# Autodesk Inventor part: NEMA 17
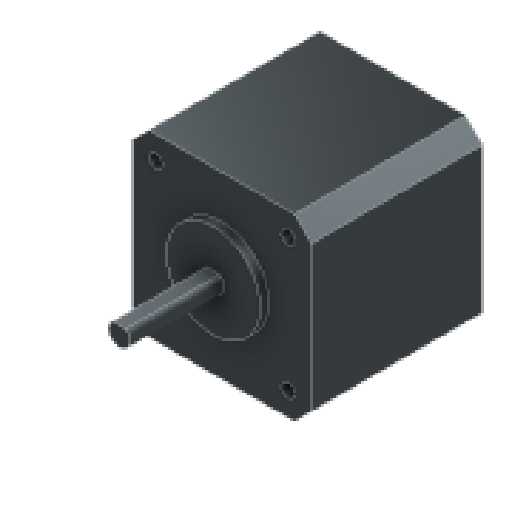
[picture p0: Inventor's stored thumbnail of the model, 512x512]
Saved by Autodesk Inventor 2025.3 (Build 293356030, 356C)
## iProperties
Created: 2026-03
Part Number: NEMA 17
Material: Generico
Description: NEMA 17
Document SubType Name: Modeling
Designer: R5800u
Density: 1 g/cm^3
Appearance: Grigio ferro
Author: R5800u
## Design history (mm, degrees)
node "NEMA 17"
sketch "Schizzo1"
  geometry: L1 (-2.707, 42)-(39.293, 42); L2 (39.293, 42)-(39.293, 0); L3 (39.293, 0)-(-2.707, 0); L4 (-2.707, 0)-(-2.707, 42); L5 (-2.707, 42)-(39.293, 0); L6 (39.293, 42)-(-2.707, 0); L7 (50.204, 58.756)-(-13.618, 58.756); L8 (-13.618, 58.756)-(-13.618, -16.756); L9 (-13.618, -16.756)-(50.204, -16.756); L10 (50.204, -16.756)-(50.204, 58.756); L11 (50.204, 58.756)-(-13.618, -16.756); L12 (-13.618, 58.756)-(50.204, -16.756); A1 r 2.5 centre (18.293, 21) between (16.793, 23) and (19.793, 23) reference; 1 further point
  constraints: 24 end point, 4 midpoint, 4 parallel, 2 horizontal, 2 perpendicular
  dimensions: "d0" = 42 distance of L2.end L3.end; "d1" = 42 distance of L1.end L2.end
extrude "Estrusione1" cut sketch "Schizzo1" extent not by distance; stored distance "d2" = 0; taper "d3" = 0 deg
sketch "Schizzo2"
  geometry: L1 (1.5, 2)-(-1.5, 2) reference; A1 r 2.5 centre (0, 0) between (-1.5, 2) and (1.5, 2) reference; 1 further point
extrude "Estrusione2" cut sketch "Schizzo2" distance "d4" = 1; taper "d5" = 0 deg
chamfer "Smusso1" distance "d6" = 4; stored, may be unused: second distance "d7" = 2, angle "d8" = 45 deg
sketch "Schizzo3"
  geometry: L1 (38, -38)-(34, -42) reference; L2 (38, -38)-(38, -4) reference; L3 (34, 0)-(38, -4) reference; L4 (34, 0)-(0, 0) reference; L5 (-4, -4)-(0, 0) reference; L6 (-4, -4)-(-4, -38) reference; L7 (0, -42)-(-4, -38) reference; L8 (0, -42)-(34, -42) reference; C1 r 1.6 at (1.5, -5.5) reference; C2 r 1.6 at (1.5, -36.5) reference; C3 r 1.6 at (32.5, -36.5) reference; C4 r 1.6 at (32.5, -5.5) reference; 1 further point
extrude "Estrusione3" join sketch "Schizzo3" distance "d9" = 2; taper "d10" = 0 deg
node "Solido1"
node "Linea chiusa proiettata1"
node "Linea chiusa proiettata2"
